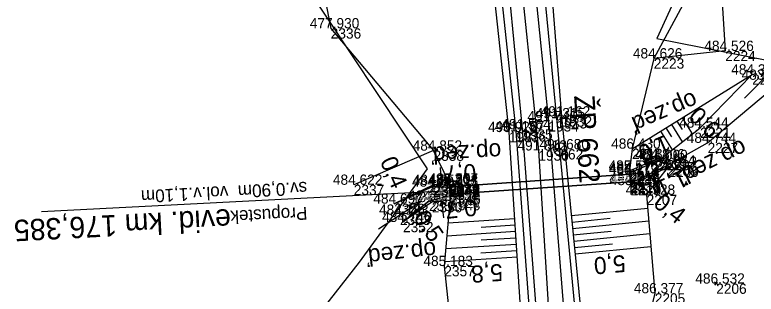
# Model space of a CAD drawing. Extents: x -1234191 to 23050, y -1290331 to -741191.
# Drawn here: x -864706.9 to -864620, y -1102544.8 to -1102512.1 of the extents above; entities that cross this region are included whole.
import ezdxf

# ---------------------------------------------------------------- set-up
doc = ezdxf.new("R2010")
doc.units = 0
for name, color, linetype in [('Vrstva 1', 7, 'Continuous'), ('Vrstva 13', 7, 'Continuous'), ('Vrstva 19', 7, 'Continuous'), ('Vrstva 4', 7, 'Continuous'), ('Vrstva 48', 7, 'Continuous'), ('Vrstva 49', 7, 'Continuous'), ('Vrstva 50', 7, 'Continuous'), ('Vrstva 53', 7, 'Continuous'), ('Vrstva 55', 7, 'Continuous'), ('Vrstva 58', 7, 'Continuous'), ('Vrstva 60', 7, 'Continuous'), ('Vrstva 61', 7, 'Continuous'), ('Vrstva 63', 7, 'Continuous')]:
    doc.layers.add(name, color=color, linetype=linetype)

msp = doc.modelspace()

# ---------------------------------------------------------------- linework, layer by layer
at = {"layer": 'Vrstva 1'}
msp.add_lwpolyline([(-864679.193, -1102400.655), (-864673.457, -1102413.519), (-864668.347, -1102426.135), (-864664.774, -1102435.919), (-864660.4, -1102449.292), (-864657.508, -1102459.219), (-864654.216, -1102471.856), (-864651.673, -1102483.426), (-864650.299, -1102490.531), (-864649.234, -1102496.745), (-864647.578, -1102508.208), (-864645.556, -1102527.952), (-864644.271, -1102547.889)], dxfattribs=at)
at = {"layer": 'Vrstva 13'}
for p, q in [((-864633.668, -1102527.636), (-864632.885, -1102529.476)), ((-864657.058, -1102529.947), (-864656.945, -1102531.944)), ((-864631.477, -1102532.653), (-864632.355, -1102530.856)), ((-864656.634, -1102535.86), (-864656.857, -1102533.873))]:
    msp.add_line(p, q, dxfattribs=at)
for points in [[(-864634.836, -1102530.562), (-864634.875, -1102530.323), (-864631.732, -1102528.985), (-864631.398, -1102529.073), (-864634.836, -1102530.562)], [(-864633.357, -1102529.133), (-864632.885, -1102529.476), (-864632.805, -1102528.898)], [(-864634.77, -1102531.768), (-864634.731, -1102532.017), (-864630.31, -1102529.858), (-864630.466, -1102529.714), (-864634.77, -1102531.768)], [(-864631.866, -1102531.174), (-864632.355, -1102530.856), (-864632.405, -1102531.437)], [(-864655.962, -1102532.041), (-864656.012, -1102531.891), (-864657.829, -1102531.994), (-864657.915, -1102532.19), (-864655.962, -1102532.041)], [(-864657.273, -1102531.462), (-864656.945, -1102531.944), (-864656.674, -1102531.428)], [(-864655.901, -1102533.216), (-864655.879, -1102533.763), (-864658.041, -1102534.006), (-864658.365, -1102533.847), (-864655.901, -1102533.216)], [(-864656.503, -1102534.336), (-864656.857, -1102533.873), (-864657.099, -1102534.403)]]:
    msp.add_lwpolyline(points, dxfattribs=at)
at = {"layer": 'Vrstva 19'}
for p, q in [((-864634.83, -1102530.742), (-864655.961, -1102532.207)), ((-864634.832, -1102530.74), (-864655.96, -1102532.207)), ((-864634.768, -1102531.643), (-864655.901, -1102533.084)), ((-864634.768, -1102531.644), (-864655.9, -1102533.085)), ((-864703.807, -1102535.108), (-864655.919, -1102532.626))]:
    msp.add_line(p, q, dxfattribs=at)
for points in [[(-864634.731, -1102532.017), (-864634.875, -1102530.323), (-864634.836, -1102530.562), (-864634.832, -1102530.74), (-864634.83, -1102530.742), (-864634.768, -1102531.643), (-864634.768, -1102531.644), (-864634.77, -1102531.768), (-864634.731, -1102532.017)], [(-864655.96, -1102531.825), (-864655.877, -1102533.426), (-864655.879, -1102533.763), (-864655.901, -1102533.216), (-864655.9, -1102533.085), (-864655.901, -1102533.084), (-864655.961, -1102532.207), (-864655.96, -1102532.207), (-864655.962, -1102532.041), (-864656.012, -1102531.891), (-864655.96, -1102531.825), (-864655.96, -1102531.825)]]:
    msp.add_lwpolyline(points, dxfattribs=at)
at = {"layer": 'Vrstva 4'}
for points in [[(-864694.545, -1102366.351), (-864686.45, -1102380.313), (-864681.373, -1102389.915), (-864662.105, -1102434.976), (-864656.956, -1102448.95), (-864651.634, -1102471.289), (-864648.937, -1102482.844), (-864645.046, -1102507.704), (-864643.414, -1102524.173), (-864641.171, -1102547.838), (-864640.651, -1102568.132), (-864639.845, -1102587.872), (-864639.918, -1102617.134), (-864639.031, -1102633.454), (-864638.752, -1102665.609), (-864639.582, -1102682.179), (-864640.261, -1102698.804), (-864641.702, -1102715.4), (-864644.496, -1102735.229), (-864648.282, -1102754.657), (-864653.396, -1102774.047), (-864660.784, -1102798.285), (-864667.606, -1102816.078), (-864675.873, -1102834.168)], [(-864685.934, -1102390.611), (-864674.848, -1102414.107), (-864666.176, -1102436.481), (-864661.941, -1102449.846), (-864655.721, -1102472.192), (-864653.269, -1102483.759), (-864649.089, -1102508.365), (-864647.449, -1102525.469), (-864645.729, -1102547.899), (-864645.062, -1102568.003), (-864644.574, -1102587.9), (-864643.788, -1102616.811), (-864643.33, -1102633.559), (-864643.057, -1102666.051), (-864643.348, -1102682.268), (-864644.136, -1102698.87), (-864645.53, -1102714.988), (-864648.306, -1102734.425), (-864652.155, -1102754.07), (-864657.013, -1102773.304), (-864664.626, -1102797.104), (-864671.163, -1102814.186), (-864679.312, -1102832.315)], [(-864682.511, -1102390.139), (-864671.933, -1102412.904), (-864663.21, -1102435.477), (-864658.841, -1102448.982), (-864652.798, -1102471.684), (-864650.223, -1102483.125), (-864646.05, -1102508.006), (-864644.385, -1102524.529), (-864642.478, -1102547.865), (-864641.884, -1102568.002), (-864641.33, -1102588.02), (-864640.64, -1102616.917), (-864640.342, -1102633.355), (-864639.964, -1102665.891), (-864640.369, -1102682.288), (-864641.19, -1102698.843), (-864642.733, -1102715.245), (-864645.498, -1102734.911), (-864649.396, -1102754.58), (-864654.231, -1102774.075), (-864661.895, -1102798.126), (-864668.541, -1102815.468), (-864676.727, -1102833.647)], [(-864686.16, -1102391.742), (-864675.749, -1102414.314), (-864667.191, -1102436.649), (-864663.097, -1102450.156), (-864656.818, -1102472.543), (-864654.162, -1102484.132), (-864650.048, -1102508.518), (-864648.213, -1102525.707), (-864646.568, -1102547.737), (-864645.816, -1102567.984), (-864645.566, -1102587.964), (-864644.916, -1102616.789), (-864644.143, -1102633.676), (-864644.088, -1102665.983), (-864644.466, -1102682.461), (-864645.558, -1102698.659), (-864646.79, -1102714.837), (-864649.436, -1102734.27), (-864653.078, -1102753.772), (-864658.002, -1102773.072), (-864665.458, -1102796.971), (-864672.144, -1102813.751), (-864680.302, -1102831.927)]]:
    msp.add_lwpolyline(points, dxfattribs=at)
at = {"layer": 'Vrstva 48'}
for p, q in [((-864628.682, -1102524.108), (-864627.511, -1102526.004)), ((-864630.597, -1102525.29), (-864629.943, -1102526.349)), ((-864629.959, -1102524.896), (-864628.696, -1102526.94)), ((-864629.32, -1102524.502), (-864628.712, -1102525.487)), ((-864631.235, -1102525.684), (-864629.881, -1102527.875)), ((-864631.72, -1102531.671), (-864632.608, -1102530.98)), ((-864632.641, -1102532.855), (-864634.109, -1102531.713)), ((-864632.181, -1102532.263), (-864632.77, -1102531.805)), ((-864659.89, -1102532.973), (-864659.873, -1102533.009)), ((-864659.213, -1102532.651), (-864659.169, -1102532.743)), ((-864660.568, -1102533.294), (-864660.543, -1102533.348)), ((-864659.33, -1102534.893), (-864659.388, -1102534.809)), ((-864658.712, -1102534.468), (-864658.862, -1102534.251)), ((-864641.681, -1102535.592), (-864632.733, -1102534.709)), ((-864659.948, -1102535.318), (-864660.029, -1102535.2)), ((-864648.345, -1102535.972), (-864656.143, -1102536.475)), ((-864641.607, -1102536.339), (-864637.139, -1102535.898)), ((-864641.534, -1102537.085), (-864632.609, -1102536.204)), ((-864648.248, -1102537.469), (-864656.274, -1102537.987)), ((-864648.296, -1102536.72), (-864652.252, -1102536.976)), ((-864641.46, -1102537.831), (-864637.004, -1102537.392)), ((-864648.2, -1102538.217), (-864652.27, -1102538.48)), ((-864641.386, -1102538.578), (-864632.486, -1102537.699)), ((-864648.151, -1102538.966), (-864656.406, -1102539.498)), ((-864641.313, -1102539.324), (-864636.868, -1102538.886)), ((-864641.239, -1102540.07), (-864632.362, -1102539.195)), ((-864648.103, -1102539.714), (-864652.287, -1102539.984)), ((-864648.055, -1102540.463), (-864656.537, -1102541.01))]:
    msp.add_line(p, q, dxfattribs=at)
at = {"layer": 'Vrstva 49'}
for p, q in [((-864634.57, -1102527.744), (-864620.49, -1102519.048)), ((-864657.843, -1102527.969), (-864667.192, -1102531.973)), ((-864632.863, -1102533.14), (-864630.31, -1102529.858)), ((-864657.829, -1102531.994), (-864662.45, -1102534.188)), ((-864657.915, -1102532.19), (-864662.45, -1102534.188)), ((-864657.915, -1102532.19), (-864657.829, -1102531.994)), ((-864655.962, -1102532.041), (-864655.96, -1102532.207)), ((-864634.731, -1102532.017), (-864632.863, -1102533.14)), ((-864658.365, -1102533.847), (-864661.419, -1102536.33)), ((-864658.041, -1102534.006), (-864661.419, -1102536.33)), ((-864658.365, -1102533.847), (-864658.041, -1102534.006)), ((-864624.519, -1102543.719), (-864624.895, -1102543.389)), ((-864624.872, -1102543.742), (-864624.542, -1102543.366))]:
    msp.add_line(p, q, dxfattribs=at)
for points in [[(-864698.694, -1102381.191), (-864696.424, -1102379.938), (-864691.979, -1102385.475), (-864686.584, -1102392.307), (-864676.44, -1102414.58), (-864667.834, -1102437.226), (-864663.667, -1102450.333), (-864657.507, -1102472.947), (-864655.013, -1102484.487), (-864650.856, -1102508.769), (-864649.001, -1102525.795), (-864647.559, -1102548.151), (-864647.098, -1102568.001), (-864646.629, -1102588.017), (-864646.304, -1102601.062)], [(-864681.373, -1102389.915), (-864662.105, -1102434.976), (-864656.956, -1102448.95), (-864651.634, -1102471.289), (-864648.937, -1102482.844), (-864644.129, -1102507.646), (-864642.828, -1102523.966), (-864640.45, -1102548.067), (-864639.806, -1102568.097), (-864638.222, -1102584.084)], [(-864626.413, -1102498.842), (-864628.383, -1102510.472), (-864632.022, -1102517.164), (-864634.57, -1102527.744), (-864634.875, -1102530.323)], [(-864626.413, -1102498.842), (-864624.456, -1102503.661), (-864623.648, -1102516.285), (-864632.022, -1102517.164)], [(-864672.058, -1102502.579), (-864669.893, -1102513.637), (-864657.843, -1102527.969)], [(-864634.875, -1102530.323), (-864631.732, -1102528.985), (-864631.398, -1102529.073), (-864626.6, -1102525.284), (-864620.49, -1102519.048)], [(-864634.731, -1102532.017), (-864630.31, -1102529.858), (-864630.466, -1102529.714), (-864625.711, -1102527.06), (-864617.004, -1102519.74), (-864613.106, -1102519.534)], [(-864655.877, -1102533.426), (-864655.96, -1102531.825), (-864657.843, -1102527.969)], [(-864632.863, -1102533.14), (-864631.907, -1102544.688), (-864635.596, -1102560.038), (-864637.196, -1102577.323), (-864638.222, -1102584.084)], [(-864655.877, -1102533.426), (-864656.58, -1102541.499), (-864655.155, -1102555.113), (-864652.502, -1102574.963), (-864648.189, -1102595.404), (-864646.304, -1102601.062)]]:
    msp.add_lwpolyline(points, dxfattribs=at)
at = {"layer": 'Vrstva 50'}
for points in [[(-864634.836, -1102530.562), (-864631.398, -1102529.073), (-864626.6, -1102525.284), (-864620.49, -1102519.048)], [(-864634.77, -1102531.768), (-864630.466, -1102529.714), (-864625.711, -1102527.06), (-864617.004, -1102519.74)], [(-864655.962, -1102532.041), (-864655.96, -1102532.207), (-864634.832, -1102530.74), (-864634.836, -1102530.562)], [(-864662.45, -1102534.188), (-864657.915, -1102532.19), (-864655.962, -1102532.041)], [(-864655.901, -1102533.216), (-864655.9, -1102533.085), (-864634.768, -1102531.644), (-864634.77, -1102531.768)], [(-864661.419, -1102536.33), (-864658.365, -1102533.847), (-864655.901, -1102533.216)]]:
    msp.add_lwpolyline(points, dxfattribs=at)
at = {"layer": 'Vrstva 53'}
for points in [[(-864685.34, -1102369.7), (-864652.19, -1102431.45), (-864651.08, -1102433.92), (-864649.81, -1102436.72), (-864644.67, -1102440.9), (-864637.86, -1102447.68), (-864634.66, -1102450.05), (-864628.74, -1102455.44), (-864614.16, -1102466.94), (-864608.82, -1102469.48), (-864608.15, -1102493.66), (-864617.6, -1102495.16), (-864625.8, -1102502.03), (-864631.68, -1102514.84), (-864618.76, -1102517.37), (-864614.67, -1102518.17), (-864613.23, -1102518.45), (-864607.97, -1102568.96), (-864604.71, -1102634.96), (-864611.4, -1102663.26), (-864622.78, -1102711.51), (-864635.49, -1102733.5), (-864648.81, -1102800.46)], [(-864676.39, -1102798.67), (-864665.19, -1102755.33), (-864652.87, -1102728.17), (-864668.04, -1102723.15), (-864663.88, -1102647.17), (-864676.76, -1102616.59), (-864673.86, -1102587.03), (-864678.04, -1102555.79), (-864666.52, -1102541.05), (-864658.56, -1102530.11), (-864673.3, -1102507.86), (-864675.68, -1102503.67), (-864677.37, -1102492.34), (-864677.91, -1102487.71), (-864684.94, -1102427.32), (-864684.87, -1102421.59), (-864685.79, -1102417.71), (-864687.98, -1102403.35)]]:
    msp.add_lwpolyline(points, dxfattribs=at)
at = {"layer": 'Vrstva 55'}
msp.add_lwpolyline([(-864685.34, -1102369.7), (-864652.19, -1102431.45), (-864635.26, -1102468.98), (-864625.8, -1102502.03), (-864631.68, -1102514.84), (-864613.23, -1102518.45), (-864607.97, -1102568.96), (-864611.13, -1102641.68), (-864611.4, -1102663.26), (-864622.78, -1102711.51), (-864635.49, -1102733.5), (-864648.81, -1102800.46), (-864676.09, -1102867.88), (-864677.03, -1102870.08)], dxfattribs=at)
at = {"layer": 'Vrstva 58'}
for p, q in [((-864621.384, -1102521.809), (-864617.184, -1102517.523)), ((-864664.291, -1102537.126), (-864659.273, -1102533.838))]:
    msp.add_line(p, q, dxfattribs=at)
msp.add_lwpolyline([(-864661.22, -1102534.516), (-864659.273, -1102533.838), (-864660.672, -1102535.352)], dxfattribs=at)
at = {"layer": 'Vrstva 60'}
for p, q in [((-864669.893, -1102513.637), (-864669.893, -1102513.637)), ((-864623.648, -1102516.285), (-864623.648, -1102516.285)), ((-864632.022, -1102517.164), (-864632.022, -1102517.164)), ((-864620.49, -1102519.048), (-864620.49, -1102519.048)), ((-864643.414, -1102524.173), (-864643.414, -1102524.173)), ((-864642.828, -1102523.966), (-864642.828, -1102523.966)), ((-864644.385, -1102524.529), (-864644.385, -1102524.529)), ((-864626.6, -1102525.284), (-864626.6, -1102525.284)), ((-864649.001, -1102525.795), (-864649.001, -1102525.795)), ((-864648.213, -1102525.707), (-864648.213, -1102525.707)), ((-864647.449, -1102525.469), (-864647.449, -1102525.469)), ((-864625.711, -1102527.06), (-864625.711, -1102527.06)), ((-864642.975, -1102527.81), (-864642.975, -1102527.81)), ((-864634.57, -1102527.744), (-864634.57, -1102527.744)), ((-864657.843, -1102527.969), (-864657.843, -1102527.969)), ((-864645.556, -1102527.952), (-864645.556, -1102527.952)), ((-864631.732, -1102528.985), (-864631.732, -1102528.985)), ((-864631.398, -1102529.073), (-864631.398, -1102529.073)), ((-864634.875, -1102530.323), (-864634.875, -1102530.323)), ((-864630.466, -1102529.714), (-864630.466, -1102529.714)), ((-864630.31, -1102529.858), (-864630.31, -1102529.858)), ((-864634.836, -1102530.562), (-864634.836, -1102530.562)), ((-864634.832, -1102530.74), (-864634.832, -1102530.74)), ((-864634.83, -1102530.742), (-864634.83, -1102530.742)), ((-864667.192, -1102531.973), (-864667.192, -1102531.973)), ((-864657.915, -1102532.19), (-864657.915, -1102532.19)), ((-864657.829, -1102531.994), (-864657.829, -1102531.994)), ((-864656.012, -1102531.891), (-864656.012, -1102531.891)), ((-864655.962, -1102532.041), (-864655.962, -1102532.041)), ((-864655.961, -1102532.207), (-864655.961, -1102532.207)), ((-864655.96, -1102531.825), (-864655.96, -1102531.825)), ((-864655.96, -1102531.825), (-864655.96, -1102531.825)), ((-864655.96, -1102532.207), (-864655.96, -1102532.207)), ((-864634.77, -1102531.768), (-864634.77, -1102531.768)), ((-864634.768, -1102531.643), (-864634.768, -1102531.643)), ((-864634.768, -1102531.644), (-864634.768, -1102531.644)), ((-864634.731, -1102532.017), (-864634.731, -1102532.017)), ((-864655.901, -1102533.084), (-864655.901, -1102533.084)), ((-864655.9, -1102533.085), (-864655.9, -1102533.085)), ((-864632.863, -1102533.14), (-864632.863, -1102533.14)), ((-864658.365, -1102533.847), (-864658.365, -1102533.847)), ((-864658.041, -1102534.006), (-864658.041, -1102534.006)), ((-864655.901, -1102533.216), (-864655.901, -1102533.216)), ((-864655.879, -1102533.763), (-864655.879, -1102533.763)), ((-864655.877, -1102533.426), (-864655.877, -1102533.426)), ((-864662.45, -1102534.188), (-864662.45, -1102534.188)), ((-864661.782, -1102535.482), (-864661.782, -1102535.482)), ((-864661.419, -1102536.33), (-864661.419, -1102536.33)), ((-864656.58, -1102541.499), (-864656.58, -1102541.499)), ((-864624.707, -1102543.554), (-864624.707, -1102543.554)), ((-864631.907, -1102544.688), (-864631.907, -1102544.688))]:
    msp.add_line(p, q, dxfattribs=at)
at = {"layer": 'Vrstva 63'}
msp.add_line((-864643.025, -1102527.81), (-864642.925, -1102527.81), dxfattribs=at)
msp.add_circle((-864642.975, -1102527.81), 0.756, dxfattribs=at)

# ---------------------------------------------------------------- texts
at = {"layer": 'Vrstva 13'}
for s, rotation, p in [('op.zeď', 203.05984, (-864627.408, -1102521.004)), ('1,0', 203.05984, (-864630.639, -1102526.053)), ('op.zeď', 183.24444, (-864649.948, -1102527.062)), ('op.zeď', 206.02862, (-864621.732, -1102526.567)), ('0,7', 183.24444, (-864652.901, -1102529.517)), ('1,1', 206.02862, (-864628.631, -1102530.1)), ('0,7', 186.4129, (-864652.9, -1102533.588)), ('op.zeď', 186.4129, (-864657.632, -1102538.607))]:
    msp.add_text(s, height=2, rotation=rotation, dxfattribs=at).set_placement(p)
at = {"layer": 'Vrstva 19'}
for s, height, p in [('sv.0,90m  vol.v.1,10m', 1.5, (-864672.694, -1102531.614)), ('evid. km 176,385', 2.5, (-864681.662, -1102534.796)), ('Propustek', 1.5, (-864672.668, -1102534.555))]:
    msp.add_text(s, height=height, rotation=182.96771, dxfattribs=at).set_placement(p)
at = {"layer": 'Vrstva 48'}
for s, rotation, p in [('0,6', 315.58473, (-864628.095, -1102524.084)), ('0,4', 293.77701, (-864664.164, -1102529.208)), ('0,4', 322.11961, (-864632.212, -1102534.41)), ('0,5', 304.52723, (-864660.266, -1102535.819)), ('5,0', 184.73243, (-864635.414, -1102540.189)), ('5,8', 183.69056, (-864649.785, -1102541.238))]:
    msp.add_text(s, height=2, rotation=rotation, dxfattribs=at).set_placement(p)
at = {"layer": 'Vrstva 60'}
for s, p in [('2336', (-864669.893, -1102514.837)), ('2224', (-864623.648, -1102517.485)), ('2223', (-864632.022, -1102518.364)), ('2222', (-864620.49, -1102520.248)), ('1933', (-864643.414, -1102525.373)), ('1932', (-864642.828, -1102525.166)), ('1934', (-864644.385, -1102525.729)), ('2221', (-864626.6, -1102526.484)), ('1937', (-864649.001, -1102526.995)), ('1936', (-864648.213, -1102526.907)), ('1935', (-864647.449, -1102526.669)), ('2227', (-864625.711, -1102528.26)), ('662', (-864642.975, -1102529.01)), ('2218', (-864634.57, -1102528.944)), ('2338', (-864657.843, -1102529.169)), ('1930', (-864645.556, -1102529.152)), ('2219', (-864631.732, -1102530.185)), ('2220', (-864631.398, -1102530.273)), ('2217', (-864634.875, -1102531.523)), ('2208', (-864630.466, -1102530.914)), ('2209', (-864630.31, -1102531.058)), ('2216', (-864634.836, -1102531.762)), ('2215', (-864634.832, -1102531.94)), ('2214', (-864634.83, -1102531.942)), ('2337', (-864667.192, -1102533.173)), ('2355', (-864657.915, -1102533.39)), ('2354', (-864657.829, -1102533.194)), ('2341', (-864656.012, -1102533.091)), ('2342', (-864655.962, -1102533.241)), ('2344', (-864655.961, -1102533.407)), ('2339', (-864655.96, -1102533.025)), ('2340', (-864655.96, -1102533.025)), ('2343', (-864655.96, -1102533.407)), ('2211', (-864634.77, -1102532.968)), ('2213', (-864634.768, -1102532.843)), ('2212', (-864634.768, -1102532.844)), ('2210', (-864634.731, -1102533.217)), ('2345', (-864655.901, -1102534.284)), ('2346', (-864655.9, -1102534.285)), ('2207', (-864632.863, -1102534.34)), ('2351', (-864658.365, -1102535.047)), ('2350', (-864658.041, -1102535.206)), ('2347', (-864655.901, -1102534.416)), ('2349', (-864655.879, -1102534.963)), ('2348', (-864655.877, -1102534.626)), ('2356', (-864662.45, -1102535.388)), ('2353', (-864661.782, -1102536.682)), ('2352', (-864661.419, -1102537.53)), ('2357', (-864656.58, -1102542.699)), ('2206', (-864624.707, -1102544.754)), ('2205', (-864631.907, -1102545.888))]:
    msp.add_text(s, height=1.2, dxfattribs=at).set_placement(p)
at = {"layer": 'Vrstva 61'}
for s, p in [('477.930', (-864672.344, -1102513.637)), ('484.526', (-864626.1, -1102516.285)), ('484.626', (-864634.474, -1102517.164)), ('484.359', (-864622.944, -1102519.048)), ('483.817', (-864621.736, -1102519.666)), ('491.746', (-864646.837, -1102524.529)), ('491.315', (-864645.87, -1102524.173)), ('491.162', (-864645.276, -1102523.966)), ('491.564', (-864649.9, -1102525.469)), ('484.544', (-864629.051, -1102525.284)), ('490.926', (-864651.453, -1102525.795)), ('491.157', (-864650.665, -1102525.707)), ('484.744', (-864628.162, -1102527.06)), ('484.852', (-864660.291, -1102527.969)), ('491.812', (-864648.004, -1102527.952)), ('491.680', (-864645.426, -1102527.81)), ('486.430', (-864637.021, -1102527.744)), ('484.806', (-864634.184, -1102528.985)), ('484.060', (-864633.849, -1102529.073)), ('484.044', (-864632.917, -1102529.714)), ('484.912', (-864632.758, -1102529.858)), ('485.576', (-864637.327, -1102530.323)), ('484.172', (-864637.284, -1102530.562)), ('484.172', (-864637.28, -1102530.74)), ('485.272', (-864637.278, -1102530.742)), ('485.261', (-864637.125, -1102531.643)), ('484.161', (-864637.125, -1102531.644)), ('484.622', (-864669.64, -1102531.973)), ('484.324', (-864660.366, -1102532.19)), ('484.757', (-864660.281, -1102531.994)), ('485.204', (-864658.463, -1102531.891)), ('484.313', (-864658.414, -1102532.041)), ('485.247', (-864658.413, -1102532.207)), ('485.557', (-864658.412, -1102531.825)), ('485.307', (-864658.412, -1102531.825)), ('484.347', (-864658.412, -1102532.207)), ('484.160', (-864637.221, -1102531.768)), ('485.559', (-864637.185, -1102532.017)), ('484.336', (-864658.353, -1102533.216)), ('485.472', (-864658.325, -1102533.426)), ('485.251', (-864658.258, -1102533.084)), ('484.351', (-864658.257, -1102533.085)), ('485.928', (-864635.317, -1102533.14)), ('484.697', (-864664.902, -1102534.188)), ('484.272', (-864660.813, -1102533.847)), ('484.807', (-864660.493, -1102534.006)), ('484.923', (-864658.331, -1102533.763)), ('484.183', (-864664.234, -1102535.482)), ('484.746', (-864663.871, -1102536.33)), ('485.183', (-864659.032, -1102541.499)), ('486.532', (-864627.155, -1102543.554)), ('486.377', (-864634.359, -1102544.688))]:
    msp.add_text(s, height=1.2, dxfattribs=at).set_placement(p)
at = {"layer": 'Vrstva 63'}
msp.add_text('ŽP 662', height=2.4, rotation=273.68779, dxfattribs=at).set_placement((-864641.375, -1102521.533))

doc.saveas('drawing.dxf')
